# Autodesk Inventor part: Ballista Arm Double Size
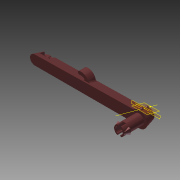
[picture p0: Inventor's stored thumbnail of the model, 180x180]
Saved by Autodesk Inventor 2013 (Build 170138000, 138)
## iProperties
Created: 2013-06
Part Number: Ballista Arm Double Size
Material: ABS Plastic
Document SubType Name: Modeling
Designer: merrill
Density: 1 g/cm^3
d7: 1.500 ul
d0_2: 145.00 deg
d1_1: 2.000 in
d2_1: 0.200 in
d3_1: 15.00 deg
d4_1: 0.300 in
d5_1: 0.00 deg
d6_1: 0.100 in
d9_1: 0.200 in
d12_1: 0.075 in
d13_1: 0.025 in
d14_1: 0.100 in
d15_1: 0.00 deg
d18_1: 0.100 in
d20_1: 0.100 in
d21_1: 20.00 deg
d22_1: 0.075 in
d24_1: 0.100 in
d25_1: 0.200 in
d26_1: 0.250 in
d27_1: 0.100 in
d28_1: 0.00 deg
d31_1: 0.150 in
d33_1: 0.040 in
d34_1: 0.040 in
d35_1: 0.00 deg
d36_1: 0.010 in
d37_1: 0.010 in
d38_1: 0.160 in
d39_1: 0.040 in
d56_1: -0.100 in
d57_1: 0.00 deg
d58_1: 0.045 in
d67_1: 0.050 in
d68_1: 0.00 deg
d69_1: 0.040 in
d70_1: 0.030 in
d71_1: 0.050 in
d72_1: 0.020 in
d74_1: 90.00 deg
Author: merrill
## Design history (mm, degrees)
derived "Ballista Arm.ipt"
  sketch "Sketch23_1"
    geometry: 3 further points; 1 other entity
    constraints: 1 horizontal alignment
  sketch "Sketch20_1"
    geometry: 2 further points; 1 other entity
    constraints: 1 vertical alignment
  workplane "Work Plane2_1"
  workplane "Work Plane3_1"
  workaxis "Work Axis1_1"
  workaxis "Work Axis3_1"
feature "Solid1::Ballista Arm.ipt_1"
tag "TaggingFeature2"
body "Solid1"
body "Solid2"
other parameters: "d7" = 1.5, "d0_2" = 145 deg, "d1_1" = 50.8, "d2_1" = 5.08, "d3_1" = 15 deg, "d4_1" = 7.62, "d5_1" = 0 deg, "d6_1" = 2.54, "d9_1" = 5.08, "d12_1" = 1.905, "d13_1" = 0.635, "d14_1" = 2.54, "d15_1" = 0 deg, "d18_1" = 2.54, "d20_1" = 2.54, "d21_1" = 20 deg, "d22_1" = 1.905, "d24_1" = 2.54, "d25_1" = 5.08, "d26_1" = 6.35, "d27_1" = 2.54, "d28_1" = 0 deg, "d31_1" = 3.81, "d33_1" = 1.016, "d34_1" = 1.016, "d35_1" = 0 deg, "d36_1" = 0.254, "d37_1" = 0.254, "d38_1" = 4.064, "d39_1" = 1.016, "d56_1" = -2.54, "d57_1" = 0 deg, "d58_1" = 1.143, "d67_1" = 1.27, "d68_1" = 0 deg, "d69_1" = 1.016, "d70_1" = 0.762, "d71_1" = 1.27, "d72_1" = 0.508, "d74_1" = 90 deg
